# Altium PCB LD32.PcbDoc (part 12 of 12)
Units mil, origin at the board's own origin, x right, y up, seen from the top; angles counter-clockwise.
Board outline 7007.87 x 4368.85 mil, 12 copper layers (Top Layer, Int1 (GND), Int2 (AVDD), Int3 (DVDD), Int4 (GND), Int5 (ST), Int6 (SB), Int8 (AGND), Int7 (AVCC), Int9 (VCCA), Int10 (GND), Bottom Layer), stack 60.136 mil thick; 1165 components, 667 nets, 3910 pads, 2570 vias.
Unrouted connection lines stored in the file: 14.
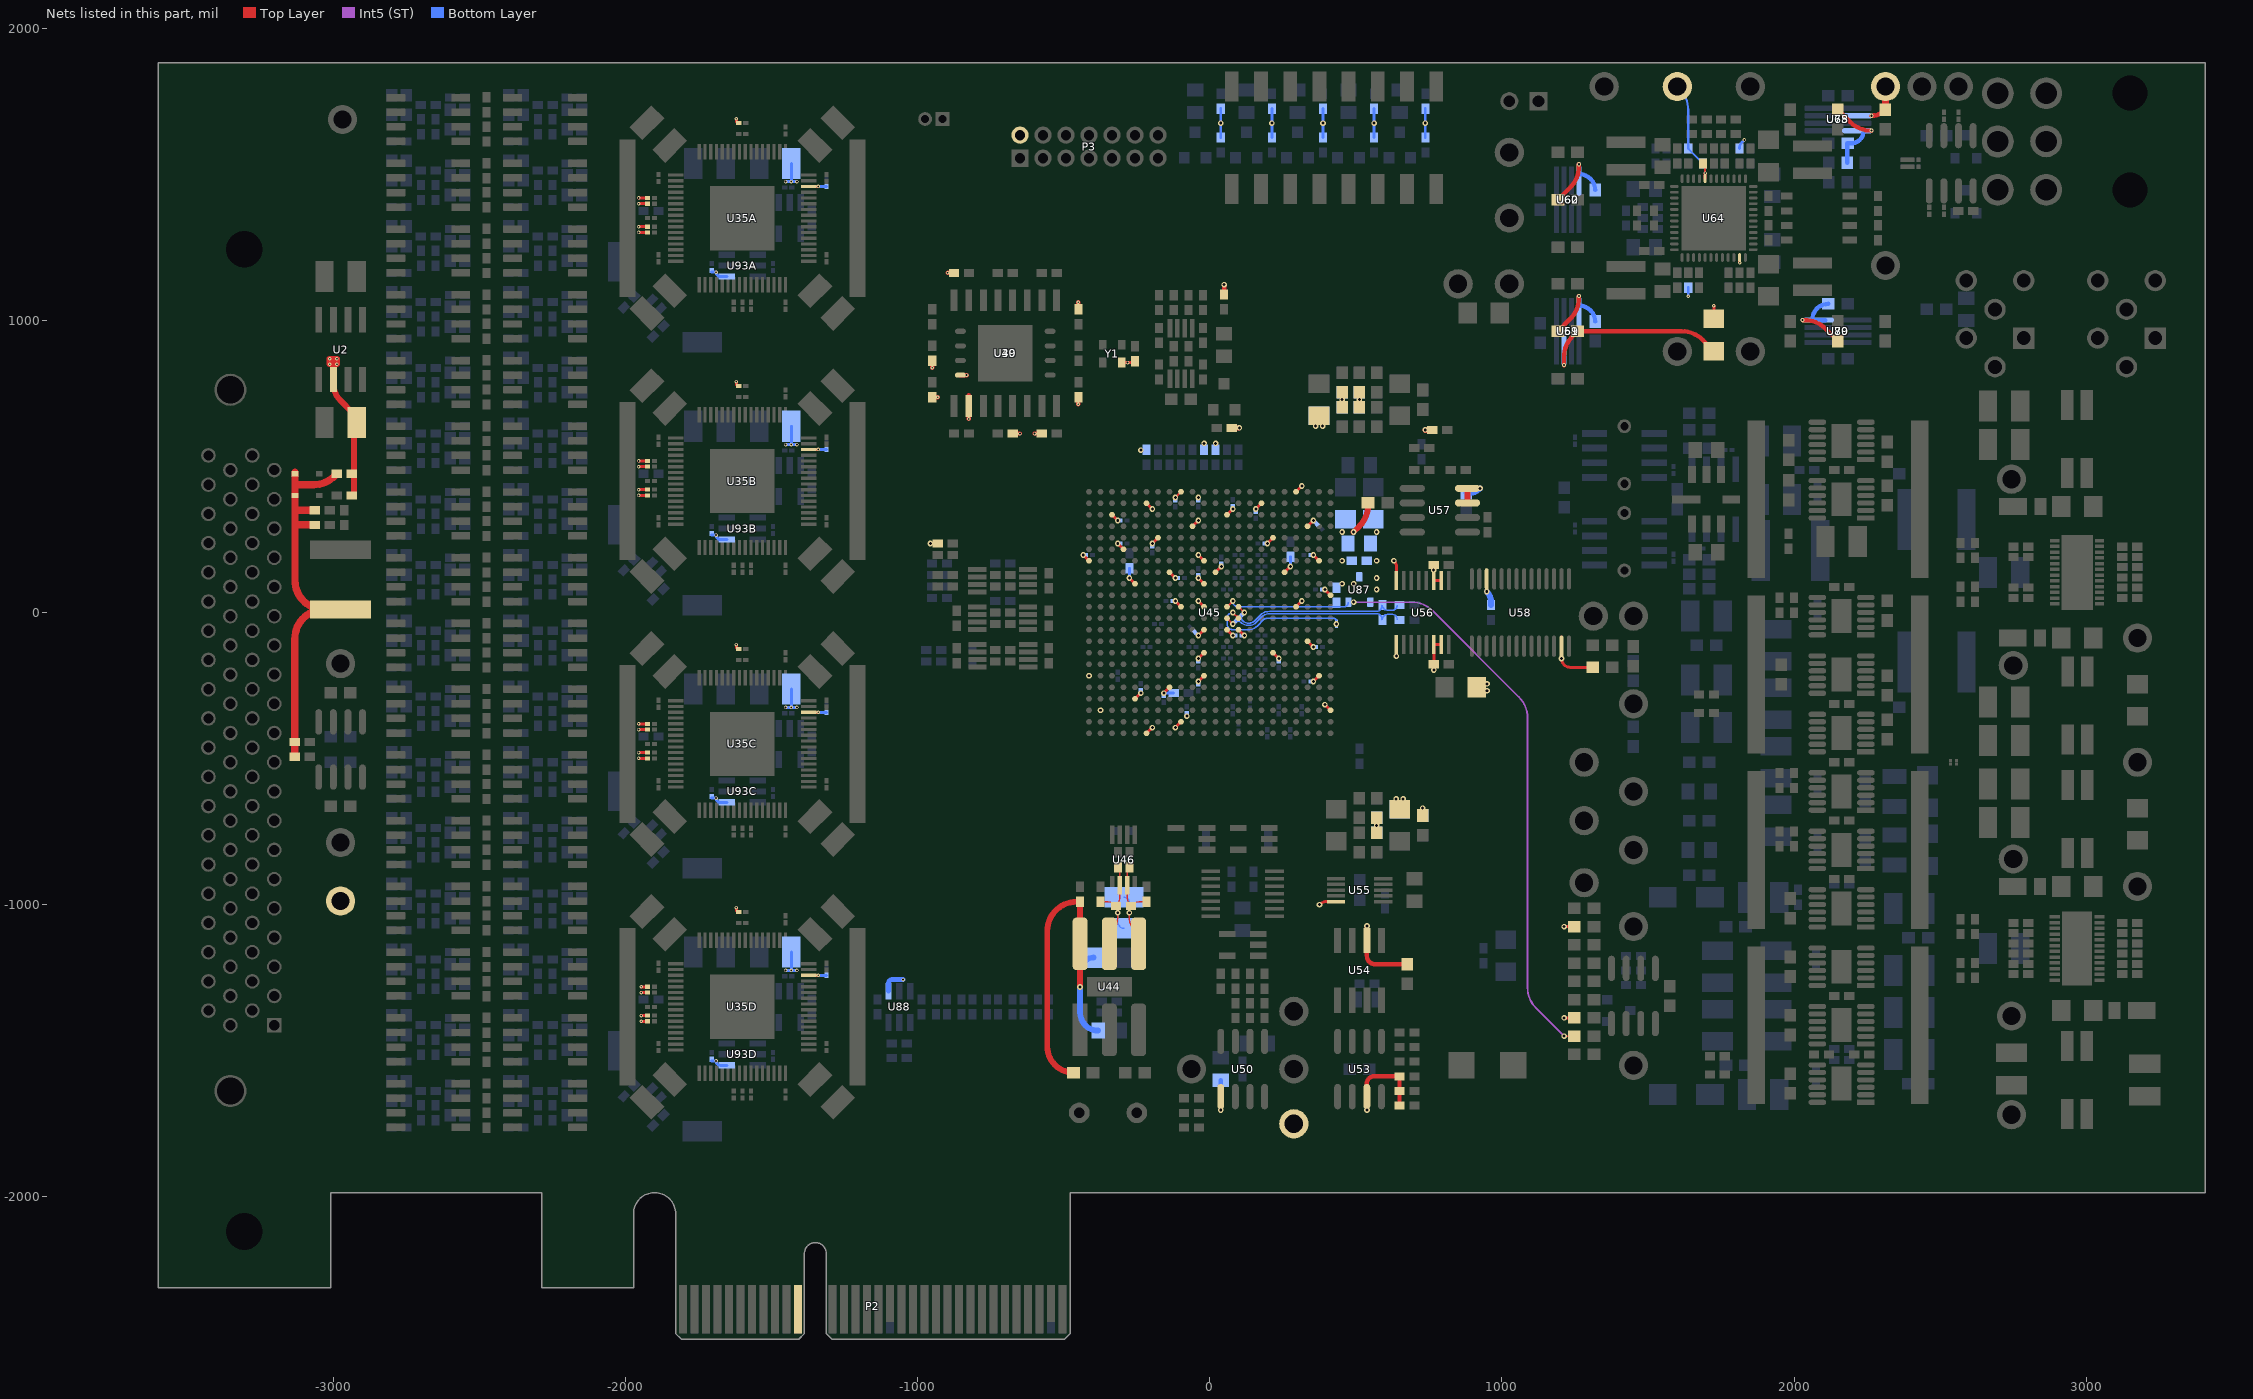
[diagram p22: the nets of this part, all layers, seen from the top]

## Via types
v1: diameter 12, hole 6, Top Layer to Bottom Layer, tented both sides, 1500 vias
v2: diameter 19, hole 10, Top Layer to Bottom Layer, tented both sides, 404 vias
v3: diameter 20, hole 10, Top Layer to Bottom Layer, tented both sides, 337 vias
v4: diameter 14, hole 7, Top Layer to Bottom Layer, tented both sides, 212 vias
v5: diameter 30, hole 15, Top Layer to Bottom Layer, tented both sides, 37 vias
v6: diameter 19.68, hole 7.87, Top Layer to Bottom Layer, 25 vias
v7: diameter 40, hole 20, Top Layer to Bottom Layer, tented both sides, 16 vias
v8: diameter 19.02, hole 10, Top Layer to Bottom Layer, tented both sides, 10 vias
v9: diameter 40, hole 20, Top Layer to Bottom Layer, 9 vias
v10: diameter 60, hole 40, Top Layer to Bottom Layer, 5 vias
v11: diameter 25, hole 13, Top Layer to Bottom Layer, 4 vias
v12: diameter 50, hole 25, Top Layer to Bottom Layer, tented both sides, 4 vias
v13: diameter 35, hole 20, Top Layer to Bottom Layer, 2 vias
v14: diameter 50, hole 25, Top Layer to Bottom Layer, 2 vias
v15: diameter 63, hole 45, Top Layer to Bottom Layer, 1 vias
v16: diameter 14.02, hole 7.01, Top Layer to Bottom Layer, tented both sides, 1 vias
v17: diameter 60, hole 40, Top Layer to Bottom Layer, tented both sides, 1 vias

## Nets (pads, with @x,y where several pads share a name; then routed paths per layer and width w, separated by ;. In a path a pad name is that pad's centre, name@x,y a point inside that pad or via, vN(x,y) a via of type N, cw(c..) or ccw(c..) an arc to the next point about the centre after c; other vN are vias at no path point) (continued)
VCCAUX: C72.2 C74.2 C75.2 C78.2 C79.2 C80.2 C81.2 C84.2 C91.2 C182.2 C185.2 C189.2 C190.2 C199.2 C200.2 C201.2 C202.2 C204.2 C205.2 C206.2 C207.2 C208.2 C209.2 C212.2 C214.2 C227.2 C228.2 C241.2 C247.2 C250.2 C251.2 C252.2 C253.2 C254.2 C256.2 C257.2 C258.2 C259.2 C260.2 C261.2 C263.2 C265.2 C268.1 C269.2 C270.2 C273.2 C287A.1 C287B.1 C287C.1 C287D.1 C291A.2 C291B.2 C291C.2 C291D.2 C307A.2 C307B.2 C307C.2 C307D.2 FR1.2 P3.2 R39A.2 R39B.2 R39C.2 R39D.2 R40A.2 R40B.2 R40C.2 R40D.2 R41A.2 R41B.2 R41C.2 R41D.2 R42A.2 R42B.2 R42C.2 R42D.2 R56A.2 R56B.2 R56C.2 R56D.2 R67.2 R68.2 R71.2 R73.1 R82.2 R85.1 R88.2 R90.2 R96.1 R107.2 R109.1 R189.1 R263.2 R280.2 R281.1 R285.2 R286.1 R288.2 R289.1 R290.2 R291.1 R295.2 R296.1 R297.2 R298.2 R304.2 TP28.1 U35A.62 U35B.62 U35C.62 U35D.62 U39.2 U40.8 U45.A17 U45.AA7 U45.AA17 U45.AB4 U45.AB14 U45.B14 U45.C1 U45.C21 U45.D18 U45.E15 U45.F2 U45.F12 U45.F22 U45.H6 U45.H12 U45.J3 U45.K12 U45.M4 U45.M12 U45.M14 U45.N1 U45.P12 U45.P18 U45.R5 U45.R11 U45.R15 U45.T2 U45.T12 U45.T22 U45.U19 U45.V6 U45.V16 U45.W3 U45.W13 U45.Y10 U45.Y20 U55.10 U65.2 U78.2 U88.1 U93A.1 U93B.1 U93C.1 U93D.1 Y1.4 | length 3834.6
  Top Layer w7.99: v2(-118.11,393.7) U45.AB14@-98.43,413.39
  Top Layer w10: v1(-1955,-499.21) R39C.2@-1933.17,-499.21 ; v1(-1955,-479.53) R40C.2@-1933.17,-479.53 ; v1(-1955,-400.79) R41C.2@-1933.17,-400.79 ; v1(-1955,-381.1) R42C.2@-1933.17,-381.1 ; v1(-1955,400.79) R39B.2@-1933.17,400.79 ; v1(-1955,420.47) R40B.2@-1933.17,420.47 ; v1(-1955,499.21) R41B.2@-1933.17,499.21 ; v1(-1955,518.9) R42B.2@-1933.17,518.9 ; v1(-1955,1300.79) R39A.2@-1933.17,1300.79 ; v1(-1955,1320.47) R40A.2@-1933.17,1320.47 ; v1(-1955,1399.21) R41A.2@-1933.17,1399.21 ; v1(-1955,1418.9) R42A.2@-1933.17,1418.9 ; v1(-1946.08,-1399.21) R39D.2@-1933.17,-1399.21 ; v1(-1946.08,-1379.53) R40D.2@-1933.17,-1379.53 ; v1(-1946.08,-1300.79) R41D.2@-1933.17,-1300.79 ; v1(-1946.08,-1281.1) R42D.2@-1933.17,-1281.1 ; v1(-1620.67,-1009.75) -1620.67,-1016.27 ccw(c-1611.94,-1016.27) R56D.2@-1611.94,-1025 ; v1(-1620.67,-109.75) -1620.67,-116.27 ccw(c-1611.94,-116.27) R56C.2@-1611.94,-125 ; v1(-1620.67,790.25) -1620.67,783.73 ccw(c-1611.94,783.73) R56B.2@-1611.94,775 ; v1(-1620.67,1690.25) -1620.67,1683.73 ccw(c-1611.94,1683.73) R56A.2@-1611.94,1675 ; U35D.62@-1372.5,-1241.73 v1(-1340,-1241.73) ; U35C.62@-1372.5,-341.73 v1(-1340,-341.73) ; U35B.62@-1372.5,558.27 v1(-1340,558.27) ; U35A.62@-1372.5,1458.27 v1(-1340,1458.27) ; v2(-956.69,236.22) R71.2@-931.1,236.22 ; v2(-433.07,196.85) U45.T22@-413.39,177.17 ; U45.Y20@-334.65,334.65 v2(-314.96,314.96) ; v2(-314.96,236.22) U45.U19@-295.28,216.54 ; Y1.4@-302.17,855.32 v1(-281.48,855.32) -267.79,855.32 ccw(c-267.79,872.12) R96.1@-255.91,860.24 ; v2(-275.59,118.11) U45.P18@-255.91,98.43 ; U45.D18@-255.91,-295.28 v2(-236.22,-275.59) ; U45.A17@-216.54,-413.39 v2(-196.85,-393.7) ; U45.AA17@-216.54,374.02 v2(-196.85,354.33) ; v2(-196.85,236.22) U45.V16@-177.17,255.91 ; v2(-157.48,-275.59) U45.E15@-137.8,-255.91 ; U45.R15@-137.8,137.8 v2(-118.11,118.11) ; v2(-118.11,-393.7) U45.B14@-98.43,-374.02 ; v2(-118.11,39.37) U45.M14@-98.43,19.69 ; U45.W13@-59.05,295.28 v2(-39.37,314.96) ; v2(-39.37,-236.22) U45.F12@-19.68,-216.54 ; v2(-39.37,-157.48) U45.H12@-19.68,-137.8 ; v2(-39.37,-78.74) U45.K12@-19.68,-59.06 ; v2(-39.37,39.37) U45.M12@-19.68,19.69 ; v2(-39.37,118.11) U45.P12@-19.68,98.43 ; v2(-39.37,196.85) U45.T12@-19.68,177.17 ; U45.R11@19.69,137.8 v2(39.37,157.48) ; U45.Y10@59.06,334.65 v2(78.74,354.33) ; v2(157.48,354.33) U45.AA7@177.17,374.02 ; v2(196.85,236.22) U45.V6@216.54,255.91 ; U45.H6@216.54,-137.8 v2(236.22,-157.48) ; U45.R5@255.91,137.8 v2(275.59,157.48) ; U45.M4@295.28,19.69 v2(314.96,39.37) ; U45.AB4@295.28,413.39 v2(314.96,433.07) ; U45.J3@334.65,-98.43 v2(354.33,-118.11) ; U45.W3@334.65,295.28 v2(354.33,314.96) ; v2(354.33,-236.22) U45.F2@374.02,-216.54 ; v2(354.33,196.85) U45.T2@374.02,177.17 ; v3(375,-1000) cw(c400.66,-1025.66) 400.66,-989.37 U55.10@431.79,-989.37 ; v2(393.7,-314.96) U45.C1@413.39,-334.65 ; v2(393.7,78.74) U45.N1@413.39,59.06 ; C74.2@452.76,702.76 v2(452.76,728.35) C75.2@452.76,753.94 ; C78.2@511.81,702.76 C79.2@511.81,753.94 ; C80.2@570.87,-753.94 C81.2@570.87,-702.76
  Top Layer w15: R67.2@-950,736.91 v1(-931.1,736.91) ; v1(-950,837.5) R68.2@-950,861.91 ; v1(-897.46,1162.5) R73.1@-875.59,1162.5 ; U40.8@-853.54,812.5 v1(-832.4,812.5) ; v1(-825,662.5) U39.2@-825,706.4 U39.2@-825,743.59 ; R82.2@-674.41,612.5 v1(-650,612.5) ; v1(-600,612.5) R85.1@-575.59,612.5 ; v1(-450,713.09) R88.2@-450,736.91 ; R90.2@-450,1038.09 v1(-450,1061.91)
  Top Layer w15.98: R109.1@49.21,1088.58 v2(49.21,1122.05) ; R107.2@74.8,631.76 v2(100.93,631.76) ; v4(2264.86,1700.3) ccw(c2264.86,1765.4) 2310.9,1719.36 R189.1@2312.5,1720.96
  Top Layer w25: R189.1@2312.5,1720.96 TP28.1@2312.5,1800
  Bottom Layer w10: C307D.2@-1705,-1535 v1(-1690,-1535) ccw(c-1675.1,-1535) -1675.1,-1549.9 U93D.1@-1653.15,-1549.9 ; C307C.2@-1705,-635 v1(-1690,-635) ccw(c-1675.1,-635) -1675.1,-649.9 U93C.1@-1653.15,-649.9 ; C307B.2@-1705,265 v1(-1690,265) ccw(c-1675.1,265) -1675.1,250.1 U93B.1@-1653.15,250.1 ; C307A.2@-1705,1165 v1(-1690,1165) ccw(c-1675.1,1165) -1675.1,1150.1 U93A.1@-1653.15,1150.1 ; v1(-1452.21,-1225) v1(-1432.38,-1225) ; v1(-1452.21,-325) v1(-1432.38,-325) ; v1(-1452.21,575) v1(-1432.38,575) ; v1(-1452.21,1475) v1(-1432.38,1475) ; C291D.2@-1432.38,-1162.5 v1(-1432.38,-1225) ; C291C.2@-1432.38,-262.5 v1(-1432.38,-325) ; C291B.2@-1432.38,637.5 v1(-1432.38,575) ; C291A.2@-1432.38,1537.5 v1(-1432.38,1475) ; v1(-1413.13,-1225) v1(-1432.38,-1225) ; v1(-1413.13,-325) v1(-1432.38,-325) ; v1(-1413.13,575) v1(-1432.38,575) ; v1(-1413.13,1475) v1(-1432.38,1475) ; v1(-1340,-1241.73) -1326.42,-1241.73 -1312.5,-1241.73 C287D.1@-1312.5,-1241.94 ; v1(-1340,-341.73) -1326.42,-341.73 -1312.5,-341.73 C287C.1@-1312.5,-341.94 ; v1(-1340,558.27) -1326.42,558.27 -1312.5,558.27 C287B.1@-1312.5,558.06 ; v1(-1340,1458.27) -1326.42,1458.27 -1312.5,1458.27 C287A.1@-1312.5,1458.06 ; v2(-275.59,118.11) C268.1@-275.59,151.57 ; v2(-157.48,-275.59) -157.48,-275.72 C257.2@-124.02,-275.72 ; R295.2@37.5,1625.59 v2(37.5,1675) R296.1@37.5,1724.41 ; R290.2@212.5,1625.59 v2(212.5,1675) R291.1@212.5,1724.41 ; v2(275.59,157.48) C212.2@275.59,190.94 ; R288.2@387.5,1625.59 v2(387.5,1675) R289.1@387.5,1724.41 ; C201.2@452.76,702.76 v2(452.76,728.35) C202.2@452.76,753.94 ; C199.2@511.81,702.76 v2(511.81,728.35) C200.2@511.81,753.94 ; R285.2@562.5,1625.59 v2(562.5,1675) R286.1@562.5,1724.41 ; C189.2@570.87,-753.94 v2(570.87,-728.35) C190.2@570.87,-702.76 ; R280.2@737.5,1625.59 v2(737.5,1675) R281.1@737.5,1724.41 ; v1(1637.5,1082.5) R263.2@1637.5,1111.91
  Bottom Layer w15.98: U88.1@-1099.9,-1296.85 -1099.9,-1268.65 cw(c-1087.5,-1268.65) -1087.5,-1256.25 v1(-1050,-1256.25)
  other v2: 728.35,-669.29 637.8,-637.8 661.42,-637.8 -78.74,-354.33 -374.02,-334.65 -413.39,-216.54 -39.37,393.7 -236.22,555.9 -19.68,578.74 19.69,578.74 362.2,637.8 385.83,637.8
  other v3: 948.82,-267.72 948.82,-244.09
VCOCLK_N: R92.2 R95.1 R97.1 TP40.1 U44.4 U46.3 | length 372.6
  Top Layer w5: R95.1@-275.59,-872.05 ccw(c-258.96,-888.68) -282.48,-888.68 U46.3@-282.48,-933.27 -282.48,-973.05 ccw(c-238.79,-973.05) R92.2@-269.68,-1003.94 ; U44.4@-246.46,-1110.24 cw(c-176.12,-1039.9) -275.59,-1039.9 v3(-275.59,-1027.56) -275.59,-1018.19 cw(c-255.43,-1018.19) R92.2@-269.68,-1003.94 ; R97.1@-216.54,-990.16 -236.42,-990.16 ccw(c-236.42,-1037.2) R92.2@-269.68,-1003.94
  Bottom Layer w5: TP40.1@-293.75,-975 cw(c-293.75,-993.16) -275.59,-993.16 v3(-275.59,-1027.56)
VCOCLK_P: R91.2 R92.1 R93.2 TP39.1 U44.5 U46.2 | length 377.1
  Top Layer w5: R91.2@-374.02,-990.16 -354.13,-990.16 cw(c-354.13,-1037.2) R92.1@-320.87,-1003.94 ; U44.5@-346.46,-1110.24 -344.25,-1108.03 ccw(c-414.96,-1037.32) -314.96,-1037.32 v3(-314.96,-1027.56) -314.96,-1018.19 ccw(c-335.12,-1018.19) R92.1@-320.87,-1003.94 ; R93.2@-314.96,-872.05 cw(c-331.59,-888.68) -308.07,-888.68 U46.2@-308.07,-933.27 -308.07,-973.05 cw(c-351.76,-973.05) R92.1@-320.87,-1003.94
  Bottom Layer w5: v3(-314.96,-1027.56) -314.96,-1058.79 ccw(c-292.5,-1058.79) TP39.1@-292.5,-1081.25
VREF1.28: C1.2 C2.1 D1.1 D2.2 R1.2 R2.2 R3.2 R5.2 | length 1436.7
  Top Layer w25: R1.2@-3131.84,-493.75 R2.2@-3131.84,-443.75 -3131.84,-89.86 cw(c-3031.84,-89.86) C1.2@-3031.84,10.14 ; D2.2@-3131.25,481.25 -3131.25,437.5 ; R3.2@-3063.09,300 -3131.25,300 ; C2.1@-3063.09,350 -3131.25,350 ; R5.2@-2988.09,475 -2996.3,466.79 cw(c-3067.01,537.5) -3067.01,437.5 -3131.25,437.5 ; C1.2@-2975,10.14 C1.2@-3031.25,10.14 ; -3131.25,300 -3131.25,350 ; -3131.25,300 -3131.25,110.14 ccw(c-3031.25,110.14) C1.2@-3031.84,10.14 ; -3131.25,350 -3131.25,437.5 ; C1.2@-3031.84,10.14 ccw(c-3031.25,110.14) C1.2@-3031.25,10.14 ; C1.2@-3031.84,10.14 C1.2@-3031.25,10.14
VREF-COM: C5.2 R4.1 R5.1 TP1.1 U2.6 | length 541
  Top Layer w20: R4.1@-2929.04,400 C5.2@-2929.04,626.07 ; C5.2@-2919.88,650 ccw(c-2967.88,650) -2933.94,683.94 -2975,725 cw(c-2914.64,785.36) -3000,785.36 U2.6@-3000,797.64 -3000,850 ; -3000,850 v1(-2987.5,850) v1(-2987.5,868.75) v1(-3012.5,868.75) v1(-3012.5,850) -3000,850
VREF-PH: C86.2 C87.2 C89.2 C248.1 R115.2 TP5.1 U50.5 U53.3 U54.6 | length 674.4
  Top Layer w15: v3(37.5,-1702.5) U50.5@37.5,-1656.99 ; U53.3@537.5,-1656.99 537.5,-1612.5 cw(c562.5,-1612.5) 562.5,-1587.5 C87.2@649.41,-1587.5 C86.2@649.41,-1637.5 R115.2@649.41,-1687.5 ; v3(537.5,-1072.5) U54.6@537.5,-1122.64 537.5,-1175 ccw(c566.54,-1175) 566.54,-1204.04 C89.2@675,-1204.04
  Bottom Layer w15: v3(37.5,-1702.5) C248.1@37.5,-1600.89
  other v3: 537.5,-1702.5
VREG: C108.1 FR3.1 R250.2 R260.2 R264.2 TP24.1 U64.23 U64.44 | length 489.9
  Top Layer w7: C108.1@1687.5,1536.91 cw(c1668.25,1517.66) 1695.47,1517.66 v1(1695.47,1504.04)
  Top Layer w10: U64.44@1695.47,1484.84 v1(1695.47,1504.04) ; FR3.1@1725,1005.12 v1(1725,1050.1) ; v1(1813.58,1197.36) U64.23@1813.58,1215.16
  Bottom Layer w7: TP24.1@1600,1800 1608.21,1791.79 cw(c1537.5,1721.08) 1637.5,1721.08 R264.2@1637.5,1590 ; R264.2@1637.5,1588.09 R264.2@1637.5,1590 ; v1(1695.47,1504.04) 1695.47,1536.91 R260.2@1687.5,1536.91 ccw(c1686.07,1536.91) 1687.08,1537.92 1639.27,1585.73 cw(c1643.54,1590) R264.2@1637.5,1590
  Bottom Layer w10: R250.2@1812.5,1588.09 cw(c1841.25,1588.09) 1820.92,1608.42 v1(1830,1617.5)
VREG2: C178.1 FR3.2 U59.7 U61.7 | length 620.8
  Top Layer w15: v4(1212.2,846.76) 1212.2,874.82 cw(c1312.2,874.82) 1241.49,945.53 C178.1@1258.46,962.5 1615.96,962.5 cw(c1615.96,862.5) 1686.67,933.21 FR3.2@1725,894.88
VVCO: C64.2 C267.2 FR9.1 R87.2 U44.6 | length 1308.5
  Top Layer w20: R87.2@-466.54,-1574.8 cw(c-466.54,-1485.09) -556.25,-1485.09 -556.25,-1090.16 cw(c-456.25,-1090.16) -456.25,-990.16 C64.2@-444.88,-990.16 -444.32,-990.72 U44.6@-444.32,-1138.94 ; v3(-443.75,-1281.25) -444.32,-1281.25 U44.6@-444.32,-1138.94 ; U44.6@-443.75,-1139.51 U44.6@-444.32,-1138.94
  Bottom Layer w20: FR9.1@-397.62,-1181.25 ccw(c-397.62,-1227.38) -443.75,-1227.38 v3(-443.75,-1281.25) -443.75,-1369.64 ccw(c-382.14,-1369.64) C267.2@-382.14,-1431.25
WAKE#: P2.B11
XADC_N: C187.2 C233.1 R283.2 U45.M9 | length 625.1
  Top Layer w5: U45.M9@98.43,19.69 v2(118.11,0)
  Bottom Layer w5: C233.1@107.61,-10.5 107.61,-14.03 ccw(c129.78,-14.03) 114.1,-29.71 114.69,-30.29 ccw(c128.35,-16.63) 128.35,-35.95 137.8,-35.95 ccw(c137.8,-16.47) 151.57,-30.24 172.5,-9.31 cw(c204.64,-41.45) 204.64,4 572.5,4 ccw(c572.5,19.56) 588.05,19.56 cw(c596.59,19.56) C187.2@590.55,25.59 ccw(c608.64,25.59) 608.64,7.5 624.04,7.5 ccw(c624.04,25) R283.2@641.54,25
XADC_P: C187.1 C233.2 R282.2 U45.L10 | length 633.4
  Top Layer w5: U45.L10@59.06,-19.68 v2(78.74,-39.37)
  Bottom Layer w5: C233.2@89.24,-28.87 92.77,-28.87 cw(c92.77,-51.04) 108.45,-35.36 109.03,-35.95 ccw(c128.35,-16.63) 128.35,-43.95 137.8,-43.95 ccw(c137.8,-16.47) 157.23,-35.9 178.16,-14.97 cw(c204.64,-41.45) 204.64,-4 572.5,-4 cw(c572.5,-19.55) 588.05,-19.55 ccw(c596.59,-19.55) C187.1@590.55,-25.59 cw(c609.9,-25.59) 609.9,-6.24 624.04,-6.24 cw(c624.04,-23.74) 641.54,-23.74 R282.2@641.54,-25
XADC_REF_N: U45.L9 W3.2 | length 482.4
  Top Layer w5: v2(78.74,0) U45.L9@98.43,-19.68
  Bottom Layer w5: v2(78.74,0) ccw(c78.74,-19.68) 59.06,-19.68 59.06,-39.37 ccw(c78.74,-39.37) 78.74,-59.06 129.64,-59.06 ccw(c129.88,-11.44) 163.55,-45.11 183.41,-25.25 cw(c196.85,-38.69) 196.85,-19.68 423.88,-19.68 cw(c423.88,-28.87) W3.2@433.07,-28.87
XADC_REF_P: C203.1 R136.1 U45.M10 U87.2 | length 2391.2
  Top Layer w5: U45.M10@59.06,19.69 v2(78.74,39.37) ; v8(1212.5,-1450) R136.1@1247.79,-1450
  Int5 (ST) w6: v2(492.13,35.43) 691.9,35.43 cw(c691.9,-64.57) 762.61,6.14 1058.21,-289.46 cw(c987.5,-360.17) 1087.5,-360.17 1087.5,-1283.58 ccw(c1187.5,-1283.58) 1116.79,-1354.29 v8(1212.5,-1450)
  Bottom Layer w5: v2(78.74,39.37) ccw(c98.43,39.37) 98.43,19.69 458.66,19.69 ccw(c458.66,35.43) U87.2@474.41,35.43
XADCGND: C93.2 C94.1 C95.1 C152.2 C155.2 C178.2 C179.2 C180.2 C193.2 C197.2 C203.2 C234.1 FR8.2 R114.1 R124.2 R125.2 R130.2 R135.2 R137.2 R176.2 R185.2 R230.2 R279.1 U45.K9 U56.2 U56.3 U56.8 U56.9 U56.14 U56.15 U57.3 U57.4 U58.12 U58.27 U59.4 U60.4 U61.4 U62.4 U65.4 U78.4 U79.4 U80.4 U87.3 W3.1 | length 1950.6
  Top Layer w10: U45.K9@98.43,-59.06 v2(118.11,-78.74) ; v2(629.92,177.17) cw(c608.54,155.78) 638.78,155.78 U56.8@638.78,109.25 ; C94.1@766.73,-177.17 U56.14@766.73,-109.25 U56.15@792.32,-109.25 ; U56.3@766.73,109.25 U56.2@792.32,109.25 ; v3(947.83,71.77) U58.12@947.83,115.16 ; U58.27@1203.74,-83.76 U58.27@1203.74,-115.16 v3(1203.74,-157.48) ccw(c1233.76,-157.48) 1233.76,-187.5 R137.2@1310.29,-187.5 ; v8(1212.5,-1387.5) R130.2@1247.79,-1387.5 ; v8(1212.5,-1075) R135.2@1247.79,-1075
  Top Layer w15: C178.2@1191.54,962.5 1234.1,1005.06 ccw(c1163.39,1075.77) 1263.39,1075.77 v4(1263.39,1083.03) ; C179.2@1191.54,1412.5 1234.1,1455.06 ccw(c1163.39,1525.77) 1263.39,1525.77 v4(1263.39,1534.3) ; v4(2029.27,1000.89) 2036.73,1000.89 cw(c2036.73,900.89) 2107.44,971.6 C152.2@2150,929.04 ; C155.2@2150,1720.96 2192.56,1678.4 ccw(c2263.27,1749.11) 2263.27,1649.11 v4(2264.86,1649.11)
  Top Layer w20: v2(492.13,275.59) 512.25,295.71 ccw(c441.54,366.42) 541.54,366.42 R114.1@541.54,375 ; v2(737.5,625) C93.2@761.91,625 ; U57.3@881.99,375 U57.4@881.99,425
  Bottom Layer w15: v4(1263.39,1083.03) U59.4@1263.39,1050.1 1264.62,1050.1 cw(c1264.62,995.96) R124.2@1318.75,995.96 ; v4(1263.39,1534.3) U60.4@1263.39,1500.1 1264.62,1500.1 cw(c1264.62,1445.96) R125.2@1318.75,1445.96 ; v4(2029.27,1000.89) U79.4@2062.4,1000.89 ; U80.4@2106.67,1000.89 U79.4@2062.4,1000.89 ; R185.2@2116.54,1056.25 ccw(c2116.54,1002.12) 2062.4,1002.12 U79.4@2062.4,1000.89 ; R230.2@2181.25,1539.71 2181.25,1604.04 cw(c2183.46,1604.04) R176.2@2183.46,1606.25 2195.96,1606.25 ccw(c2195.96,1647.88) 2237.6,1647.88 U65.4@2237.6,1649.11
  Bottom Layer w20: R279.1@877.5,408.46 885.08,408.46 ccw(c885.08,464.92) v2(925,425) ; v3(947.83,71.77) cw(c912.43,36.37) 962.5,36.37 C180.2@962.5,25.59
  other v2: 766.73,-196.85 638.78,-149.12 433.07,-39.37 452.76,98.43 492.13,98.43 766.26,145 452.76,177.17 452.76,275.59
XADCVCC: C193.1 C197.1 C234.2 FR7.2 U45.K10 U87.1 | length 27.8
  Top Layer w10: U45.K10@59.06,-59.06 v2(78.74,-78.74)
  other v2: 570.87,78.74 570.87,118.11 570.87,177.17 570.87,275.59
pads on no net: J2.MH1 J2.MH2 P2.A19 P2.A32 P2.B12 P2.B17 P2.B30 P3.12 P3.14 U2.1 U2.3 U2.5 U2.7 U2.8 U39.4 U39.5 U39.6 U39.11 U39.12 U39.13 U39.14 U41.1 U41.4 U42.1 U43.1 U43.4 U45.A13 U45.A14 U45.A16 U45.A20 U45.AA4 U45.AA9 U45.AA10 U45.AA11 U45.AA13 U45.AA14 U45.AA15 U45.AA16 U45.AB10 U45.AB11 U45.AB12 U45.AB13 U45.AB15 U45.AB16 U45.AB17 U45.AB18 U45.B13 U45.B15 U45.B16 U45.C2 U45.C13 U45.C14 U45.C15 U45.C17 U45.C18 U45.D1 U45.D2 U45.D14 U45.D15 U45.D16 U45.D17 U45.D19 U45.D20 U45.E1 U45.E2 U45.E3 U45.E10 U45.E13 U45.E14 U45.E16 U45.E17 U45.E18 U45.E19 U45.E22 U45.F1 U45.F3 U45.F4 U45.F10 U45.F13 U45.F14 U45.F15 U45.F16 U45.F18 U45.F19 U45.G1 U45.G2 U45.G3 U45.G4 U45.G17 U45.G18 U45.H2 U45.H3 U45.H4 U45.H5 U45.H14 U45.H15 U45.H17 U45.H18 U45.J2 U45.J4 U45.J5 U45.J6 U45.J14 U45.J15 U45.J16 U45.J17 U45.K2 U45.K3 U45.K4 U45.K6 U45.K13 U45.K14 U45.K16 U45.K17 U45.L3 U45.L4 U45.L5 U45.L6 U45.L13 U45.L14 U45.L15 U45.L16 U45.L18 U45.M2 U45.M3 U45.M5 U45.M6 U45.M13 U45.M15 U45.M16 U45.M17 U45.M18 U45.M20 U45.N2 U45.N3 U45.N4 U45.N5 U45.N13 U45.N14 U45.N15 U45.N17 U45.N18 U45.N19 U45.N20 U45.P1 U45.P2 U45.P4 U45.P5 U45.P6 U45.P14 U45.P15 U45.P16 U45.P17 U45.P19 U45.R1 U45.R6 U45.R14 U45.R16 U45.R17 U45.R18 U45.T3 U45.T4 U45.T5 U45.T6 U45.T14 U45.T15 U45.T16 U45.T18 U45.T20 U45.U3 U45.U5 U45.U6 U45.U7 U45.U15 U45.U16 U45.U17 U45.V4 U45.V5 U45.V7 U45.V8 U45.V9 U45.V10 U45.V13 U45.V14 U45.V15 U45.W1 U45.W6 U45.W7 U45.W9 U45.W10 U45.W11 U45.W12 U45.W14 U45.W15 U45.W16 U45.W17 U45.Y1 U45.Y4 U45.Y6 U45.Y7 U45.Y8 U45.Y11 U45.Y12 U45.Y13 U45.Y14 U45.Y16 U45.Y17 U45.Y19 U46.1 U46.4 U47.1 U49.6 U49.8 U54.1 U54.3 U54.5 U54.7 U54.8 U58.2 U58.3 U58.13 U66.4 U66.7 U68.5 U69.3 U70.3 U71.3 U72.3 U73.3 U73.5 U74.3 U75.3 U76.3 U76.5 U82.4 U82.9 U82.14 U83.4 U83.9 U83.14 U84.1 U84.5 U84.8 U85.1 U85.5 U85.8 U86.1 U86.5 U86.8

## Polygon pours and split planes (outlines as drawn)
AGND on Bottom Layer "AGND_L12_P413" (solid, pour order 413): 1377.95,-1800 1377.95,775 2418.75,775 2418.75,-1800
GND on Bottom Layer "GND_L12_P377" (solid, remove dead copper, pour order 377): 1348.43,1868.75 -1150,1868.75 -1150,-1850.01 -1237.49,-1937.5 -787.5,-1937.5 -650,-1800 1348.43,-1800
GND on Bottom Layer "GND_L12_P414" (solid, pour order 414): 2457.85,-1800 3276.6,-1800 3276.6,775 2457.85,775
AGND on Bottom Layer "AGND_L12_P323" (solid, remove dead copper, pour order 323): -3587.5,1867.5 -1175,1867.5 -1175,-1937.5 -3587.5,-1937.5
EXT12V on Bottom Layer "EXT12V_L12_P417" (solid, pour order 417): 2362.5,1475.23 2412.5,1475.23 2412.5,1533.75 2362.5,1533.75 2362.5,1515.23
12V on Bottom Layer "12V_L12_P416" (solid, pour order 416): 2362.5,1541.25 2412.5,1541.25 2412.5,1600 2362.5,1600 2362.5,1581.25
XADCGND on Bottom Layer "XADCGND_L12_P300" (solid, pour order 300): 413.39,66.93 523.62,66.93 523.62,145.67 503.94,165.35 503.94,354.33 413.39,354.33
XADCVCC on Bottom Layer "XADCVCC_L12_P321" (solid, pour order 321): 519.69,354.33 519.69,157.48 531.5,145.67 531.5,19.69 570.87,19.69 570.87,59.06 594.49,82.68 594.49,354.33
GND on Bottom Layer "GND_L12_P375" (solid, pour order 375): 1897.5,1522.5 1897.5,1467.5 1952.5,1467.5 1952.5,1522.5
VCC on Bottom Layer "VCC_L12_P376" (solid, pour order 376): -50,-1050 -50,-920 275,-920 275,-1050
GND on Bottom Layer "GND_L12_P374" (solid, pour order 374): 1952.5,1177.5 1952.5,1232.5 1897.5,1232.5 1897.5,1177.5
AGND on Top Layer "NONET_L-01_P-001" (solid, pour order 412): 2531.25,-1781.25 1631.25,-1781.25 1631.25,775 2531.25,775
AGND on Top Layer "AGND_L01_P301" (solid, remove dead copper, pour order 301): -3556.25,1867.5 -1086.25,1867.5 -1086.25,-1929 -2016.82,-1929 -3556.25,-1929
NetD3_2 on Top Layer "NETD3_2_L01_P419" (solid, pour order 419): 2412.5,1533.75 2362.5,1533.75 2362.5,1475 2412.5,1475 2412.5,1493.75
12V on Top Layer "12V_L01_P418" (solid, pour order 418): 2362.5,1541.25 2412.5,1541.25 2412.5,1600 2362.5,1600 2362.5,1581.25
GND on Top Layer "GND_L01_P409" (solid, pour order 409): 2706.25,-500 2706.25,-243.75 2556.25,-243.75 2556.25,-500
GND on Top Layer "GND_L01_P408" (solid, pour order 408): 3131.25,651.25 2977.5,651.25 2977.5,775 3131.25,775
GND on Top Layer "GND_L01_P410" (solid, pour order 410): 2706.27,518.75 2706.27,775 2556.27,775 2556.27,518.75
NetC123_1 on Top Layer "NETC123_1_L01_P405" (solid, pour order 405): 2725,-525 2960,-525 2960,-650 2725,-650
NetC124_1 on Top Layer "NETC124_1_L01_P393" (solid, pour order 393): 2960,-500 2725,-500 2725,-375 2960,-375
GND on Top Layer "GND_L01_P404" (solid, pour order 404): 3075,-500 2977.5,-500 2977.5,-375 3075,-375
GND on Top Layer "GND_L01_P402" (solid, pour order 402): 2556.25,-781.42 2706.25,-781.42 2706.25,-525 2556.25,-525
GND on Top Layer "GND_L01_P406" (solid, pour order 406): 2977.5,-525 3075,-525 3075,-650 2977.5,-650
GND on Top Layer "GND_L01_P403" (solid, pour order 403): 2687.5,-1550 2800,-1550 2800,-1325 2687.5,-1325
GND on Top Layer "GND_L01_P394" (solid, pour order 394): 3141.25,-1587.5 3141.25,-1325 3256.25,-1325 3256.25,-1587.5
NetC123_1 on Top Layer "NETC123_1_L01_P392" (solid, pour order 392): 2978.75,-1662.5 3141.25,-1662.5 3141.25,-1612.5 3256.25,-1612.5 3256.25,-1781.25 2978.75,-1781.25
NetC124_1 on Top Layer "NETC124_1_L01_P407" (solid, pour order 407): 2960,651.25 2718.75,651.25 2718.75,775 2960,775
SW-10V on Top Layer "SW-10V_L01_P401" (solid, pour order 401): 2556.25,-1781.25 2556.25,-1243.75 2581.25,-1243.75 2581.25,-1325 2668.75,-1325 2668.75,-1781.25
NetC136_1 on Top Layer "NETC136_1_L01_P400" (solid, pour order 400): 2818.75,312.5 2818.75,531.25 2960,531.25 2960,312.5
NetC134_1 on Top Layer "NETC134_1_L01_P399" (solid, pour order 399): 2818.75,-975 2818.75,-768.75 2960,-768.75 2960,-975
NetC136_2 on Top Layer "NETC136_2_L01_P398" (solid, pour order 398): 2881.25,243.75 2903.75,243.75 2903.75,275 3033.75,275 3033.75,243.75 3056.25,243.75 3056.25,531.25 2977.5,531.25 2977.5,293.75 2881.25,293.75
NetC134_2 on Top Layer "NETC134_2_L01_P397" (solid, pour order 397): 2881.25,-1043.75 2903.75,-1043.75 2903.75,-1012.5 3033.75,-1012.5 3033.75,-1043.75 3056.25,-1043.75 3056.25,-768.75 2977.5,-768.75 2977.5,-993.75 2881.25,-993.75
NetC126_1 on Top Layer "NETC126_1_L01_P396" (solid, pour order 396): 2556.25,500 2718.75,500 2718.75,630 2806.25,630 2806.25,312.5 2581.25,312.5 2581.25,237.5 2556.25,237.5
SW+10V on Top Layer "SW+10V_L01_P395" (solid, pour order 395): 2806.25,-665 2806.25,-975 2581.25,-975 2581.25,-1050.1 2556.25,-1049.92 2556.25,-800 2725,-800 2725,-665
NetC125_2 on Top Layer "NETC125_2_L01_P391" (solid, pour order 391): 2556.25,-226.25 2725,-226.25 2725,-359.89 2806.25,-359.89 2806.25,-37.5 2581.25,-37.5 2581.25,37.5 2556.25,37.5 2556.25,-37.5
SW-10V on Top Layer "SW-10V_L01_P390" (solid, pour order 390): 2556.25,-1781.25 2958.75,-1781.25 2958.75,-1662.5 2800,-1662.5 2800,-1575 2556.25,-1575
NetC135_1 on Top Layer "NETC135_1_L01_P389" (solid, pour order 389): 2818.75,-256.25 2818.75,-37.5 2960,-37.5 2960,-256.25
NetC133_1 on Top Layer "NETC133_1_L01_P388" (solid, pour order 388): 2978.75,-1537.5 2978.75,-1325 3118.75,-1325 3118.75,-1537.5
NetC135_2 on Top Layer "NETC135_2_L01_P387" (solid, pour order 387): 2881.25,31.25 2881.25,-18.75 2977.5,-18.75 2977.5,-256.25 3056.25,-256.25 3056.25,31.25 3033.75,31.25 3033.75,0 2903.75,0 2903.75,31.25
NetC133_2 on Top Layer "NETC133_2_L01_P386" (solid, pour order 386): 2881.25,-1256.25 2881.25,-1325 2881.25,-1537.5 2958.75,-1537.5 2958.75,-1306.25 3056.25,-1306.25 3056.25,-1256.25 3033.75,-1256.25 3033.75,-1287.5 2903.75,-1287.5 2903.75,-1256.25
NetC115_2 on Top Layer "NETC115_2_L01_P366" (solid, pour order 366): 2137.23,1535.47 2137.23,1362.97 1987.23,1362.97 1987.23,1535.47
NetC114_2 on Top Layer "NETC114_2_L01_P365" (solid, pour order 365): 1987.5,1165 1987.5,1337.5 2137.5,1337.5 2137.5,1165
AVCC3.3V on Top Layer "AVCC3.3V_L01_P249" (solid, pour order 249): -1833.77,-1533.73 -1783.75,-1583.75 -1815,-1615 -1865.02,-1564.98
DVDD1.2V on Top Layer "DVDD1.2V_L01_P257" (solid, pour order 257): -1416.2,-1583.7 -1366.36,-1533.86 -1335.11,-1565.11 -1384.95,-1614.95
DVDD1.2V on Top Layer "DVDD1.2V_L01_P253" (solid, pour order 253): -1878.75,-1146.25 -1803.75,-1071.25 -1772.5,-1102.5 -1847.5,-1177.5
AVCC3.3V on Top Layer "AVCC3.3V_L01_P261" (solid, pour order 261): -1352.5,-1177.5 -1427.5,-1102.5 -1396.25,-1071.25 -1321.25,-1146.25
AVCC3.3V on Top Layer "AVCC3.3V_L01_P248" (solid, pour order 248): -1846.25,-621.25 -1771.25,-696.25 -1802.5,-727.5 -1877.5,-652.5
DVDD1.2V on Top Layer "DVDD1.2V_L01_P256" (solid, pour order 256): -1428.75,-696.25 -1353.75,-621.25 -1322.5,-652.5 -1397.5,-727.5
DVDD1.2V on Top Layer "DVDD1.2V_L01_P252" (solid, pour order 252): -1878.75,-246.25 -1803.75,-171.25 -1772.5,-202.5 -1847.5,-277.5
AVCC3.3V on Top Layer "AVCC3.3V_L01_P260" (solid, pour order 260): -1352.5,-277.5 -1427.5,-202.5 -1396.25,-171.25 -1321.25,-246.25
AVCC3.3V on Top Layer "AVCC3.3V_L01_P247" (solid, pour order 247): -1846.25,278.75 -1771.25,203.75 -1802.5,172.5 -1877.5,247.5
DVDD1.2V on Top Layer "DVDD1.2V_L01_P255" (solid, pour order 255): -1428.75,203.75 -1353.75,278.75 -1322.5,247.5 -1397.5,172.5
DVDD1.2V on Top Layer "DVDD1.2V_L01_P251" (solid, pour order 251): -1878.75,653.75 -1803.75,728.75 -1772.5,697.5 -1847.5,622.5
AVCC3.3V on Top Layer "AVCC3.3V_L01_P259" (solid, pour order 259): -1352.5,622.5 -1427.5,697.5 -1396.25,728.75 -1321.25,653.75
AVCC3.3V on Top Layer "AVCC3.3V_L01_P258" (solid, pour order 258): -1352.5,1522.5 -1427.5,1597.5 -1396.25,1628.75 -1321.25,1553.75
DVDD1.2V on Top Layer "DVDD1.2V_L01_P250" (solid, pour order 250): -1878.75,1553.75 -1803.75,1628.75 -1772.5,1597.5 -1847.5,1522.5
DVDD1.2V on Top Layer "DVDD1.2V_L01_P254" (solid, pour order 254): -1428.75,1103.75 -1353.75,1178.75 -1322.5,1147.5 -1397.5,1072.5
AVCC3.3V on Top Layer "AVCC3.3V_L01_P246" (solid, pour order 246): -1846.25,1178.75 -1771.25,1103.75 -1802.5,1072.5 -1877.5,1147.5
AVCC on Int6 (SB) "AVCC_L07_P383" (solid, pour order 383): 94.49,-334.65 133.86,-295.28 177.17,-295.28 216.54,-334.65 275.59,-334.65 295.28,-314.96 389.76,-314.96 783.46,-708.66 2056.25,-708.66 2056.25,-511.81 1141.73,-511.81 787.4,-157.48 78.74,-157.48 0,-236.22 0,-334.65
SW+2V on Int6 (SB) "SW+2V_L07_P415" (solid, pour order 415): 2298.75,-305 2298.75,-821.25 2358.75,-821.25 2358.75,-305
VREF-PH on Int6 (SB) "VREF-PH_L07_P379" (solid, pour order 379): 0,-1781.25 0,-1400.94 360.94,-1040 767.72,-1040 767.72,-1781.25
XADCVCC on Int6 (SB) "XADCVCC_L07_P381" (solid, pour order 381): 55.12,-15.75 55.12,-102.36 488.19,-102.36 610.24,19.68 610.24,295.28 590.55,314.96 551.18,314.96 531.5,295.28 531.5,51.18 464.57,-15.75
AVTT on Int6 (SB) "AVTT_L07_P382" (solid, pour order 382): 98.43,-354.33 137.8,-314.96 177.17,-314.96 216.54,-354.33 275.59,-354.33 295.28,-334.65 383.86,-334.65 777.56,-728.35 2056.25,-728.35 2056.25,-905.51 1023.62,-905.51 452.76,-905.51 0,-452.76 0,-354.33
SENS_120f_N on Int6 (SB) "SENS_120F_N_L07_P367" (solid, pour order 367): 1978.35,1162.5 1978.35,1594.49 1456.69,1594.49 1456.69,1162.5
VREG on Int5 (ST) "VREG_L06_P378" (solid, pour order 378): 1993.75,1037.5 1993.75,1850 1437.5,1850 1437.5,1037.5
GND on Int1 (GND) (split plane): 113 vertices, not listed, extent -3579.9,-2467.4 3387.78,1861.25
VREF-COM on Int2 (AVDD) (split plane): 94 vertices, not listed, extent -3579.9,-2290.24 -1939.81,1861.25
COM1&2 on Int2 (AVDD) (split plane): 22 vertices, not listed, extent -3027.41,-227.41 -2110.09,1861.25
COM3&4 on Int2 (AVDD) (split plane): 24 vertices, not listed, extent -3033.66,-1789.91 -2110.09,-10.09
VCCAUX on Int2 (AVDD) (split plane): 55 vertices, not listed, extent -2092.1,-1964.91 2714.91,1861.25
EXTGND on Int2 (AVDD) (split plane): 124 vertices, not listed, extent -1843.53,-2467.4 3387.78,1861.25
NetC124_1 on Int2 (AVDD) (split plane): 19 vertices, not listed, extent 2460.09,-502.41 3252.41,1227.41
NetC123_1 on Int2 (AVDD) (split plane): 3252.41,-1770.82 3233.32,-1789.91 2460.09,-1789.91 2460.09,-522.59 3252.41,-522.59
AGND on Int3 (DVDD) (split plane): 52 vertices, not listed, extent -3579.9,-2290.24 -1939.81,1861.25
EXTGND on Int3 (DVDD) (split plane): 140 vertices, not listed, extent -1843.53,-2467.4 3387.78,1861.25
AGND on Int3 (DVDD) (split plane): -2110.09,-1783.32 -2116.68,-1789.91 -2845.82,-1789.91 -2852.41,-1783.32 -2852.41,1861.25 -2110.09,1861.25
DVDD1.2V on Int3 (DVDD) (split plane): 68 vertices, not listed, extent -2092.1,-1964.91 2439.91,1861.25
VCC2 on Int3 (DVDD) (split plane): 58 vertices, not listed, extent -1164.91,-1539.91 2714.91,1861.25
12VA on Int3 (DVDD) (split plane): 23 vertices, not listed, extent 2460.09,-1789.91 3252.41,1227.41
AVCC1V8 on Int3 (DVDD) (split plane): 39 vertices, not listed, extent 527.59,457.59 1577.41,1427.41
VCC1V0 on Int3 (DVDD) (split plane): 80 vertices, not listed, extent 10.09,-186.76 2264.91,1577.41
AGND on Int4 (GND) (split plane): 44 vertices, not listed, extent -3579.9,-2290.24 -1939.81,1861.25
GND on Int4 (GND) (split plane): 184 vertices, not listed, extent -2089.91,-1964.91 3252.41,1861.25
EXTGND on Int4 (GND) (split plane): 97 vertices, not listed, extent -1843.53,-2467.4 3387.78,764.91
XADCGND on Int4 (GND) (split plane): 101 vertices, not listed, extent 110.09,-1539.91 2364.91,1861.25
12V on Int4 (GND) (split plane): 45 vertices, not listed, extent 2385.09,785.09 3387.78,1861.25
EXTGND on Int8 (AGND) (split plane): 97 vertices, not listed, extent -1843.53,-2467.4 3387.78,764.91
AGND on Int8 (AGND) (split plane): 96 vertices, not listed, extent -3579.9,-2290.24 2439.91,1861.25
GND on Int8 (AGND) (split plane): 67 vertices, not listed, extent -1164.91,-1789.91 3252.41,1861.25
12V on Int8 (AGND) (split plane): 30 vertices, not listed, extent 2385.09,785.09 3387.78,1861.25
+7V on Int7 (AVCC) (split plane): 120 vertices, not listed, extent -3579.9,-2290.24 2439.91,1861.25
AVCC3.3V on Int7 (AVCC) (split plane): 43 vertices, not listed, extent -2089.91,-1789.91 2383.66,1861.25
EXTGND on Int7 (AVCC) (split plane): 125 vertices, not listed, extent -1843.53,-2467.4 3387.78,1861.25
VCC2V5 on Int7 (AVCC) (split plane): 32 vertices, not listed, extent -1164.91,-1352.41 2714.91,1861.25
GND on Int7 (AVCC) (split plane): 22 vertices, not listed, extent 2460.09,-1789.91 3252.41,1227.41
-7V on Int9 (VCCA) (split plane): 117 vertices, not listed, extent -3579.9,-2290.24 2439.91,1861.25
VCCA3.3V on Int9 (VCCA) (split plane): 43 vertices, not listed, extent -2089.92,-1789.91 2383.66,1861.25
EXTGND on Int9 (VCCA) (split plane): 133 vertices, not listed, extent -1843.53,-2467.4 3387.78,1861.25
VCC on Int9 (VCCA) (split plane): 31 vertices, not listed, extent -1164.91,-1352.41 2714.91,1861.25
GND on Int9 (VCCA) (split plane): 27 vertices, not listed, extent 2460.09,-1789.91 3252.41,1227.41
GND on Int10 (GND) (split plane): 113 vertices, not listed, extent -3579.9,-2467.4 3387.78,1861.25

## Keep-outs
Top Layer:
  rectangle: -3600,1042.5 -3100,1867.5
  rectangle: -477.5,-1985.53 3407.87,-1946.16
  region: -3600,-2312.32 -3009.45,-2312.32 ccw(c-3009.45,-2310.33) -3007.47,-2310.33 -3007.47,-1987.51 -2288.99,-1987.51 -2288.99,-2174.51 ccw(c-2287.01,-2174.51) -2287.01,-2176.49 -1972.05,-2176.49 ccw(c-1972.05,-2174.51) -1970.06,-2174.51 -1970.06,-2057.38 cw(c-1900.2,-2057.38) -1830.33,-2057.38 ccw(c-1828.35,-2057.38) -1826.36,-2057.38 -1826.36,-1946.16 ccw(c-1828.35,-1946.16) -1828.35,-1944.18 -3600,-1944.18 ccw(c-3600,-1946.16) -3601.98,-1946.16 -3601.98,-2310.33 ccw(c-3600,-2310.33)
Bottom Layer:
  rectangle: -477.5,-1985.53 3407.5,-1946.16
  rectangle: -3600,1042.5 -3100,1867.5
  region: -3600,-2312.32 -3009.45,-2312.32 ccw(c-3009.45,-2310.33) -3007.47,-2310.33 -3007.47,-1987.51 -2288.99,-1987.51 -2288.99,-2174.51 ccw(c-2287.01,-2174.51) -2287.01,-2176.49 -1972.05,-2176.49 ccw(c-1972.05,-2174.51) -1970.06,-2174.51 -1970.06,-2057.38 cw(c-1900.2,-2057.38) -1830.33,-2057.38 ccw(c-1828.35,-2057.38) -1826.36,-2057.38 -1826.36,-1946.16 ccw(c-1828.35,-1946.16) -1828.35,-1944.18 -3600,-1944.18 ccw(c-3600,-1946.16) -3601.98,-1946.16 -3601.98,-2310.33 ccw(c-3600,-2310.33)
Top Solder:
  rectangle: -2287.01,-2310.33 -1972.05,-2174.51
Bottom Solder:
  rectangle: -2287.01,-2310.33 -1972.05,-2174.51
KeepOutLayer:
  rectangle: -1787.5,-1537.5 -1412.5,-1162.5
  rectangle: -1787.5,1162.5 -1412.5,1537.5
  rectangle: -1787.5,262.5 -1412.5,637.5
  rectangle: -1787.5,-637.5 -1412.5,-262.5
  rectangle: -2287.01,-2310.33 -1972.05,-2174.51

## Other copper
Top Layer:
  rectangle net AGND: 2506.25,-537.5 2531.25,-487.5
  rectangle net GND: 2556.25,-537.5 2581.25,-487.5
  region net AGND: -3257.28,887.5 -3600,887.5 -3600,651.28 -3367.65,651.28 -3352.3,653.3 -3337.35,657.31 -3323.04,663.23 -3309.63,670.97 -3297.35,680.4 -3286.4,691.35 -3276.98,703.63 -3269.24,717.04 -3263.31,731.34 -3259.3,746.3 -3257.28,761.65 -3257.28,769.39
  region net AGND: -3257.28,-1762.5 -3600,-1762.5 -3600,-1526.28 -3375.39,-1526.28 -3367.65,-1526.28 -3352.3,-1528.3 -3337.35,-1532.31 -3323.04,-1538.23 -3309.63,-1545.97 -3297.35,-1555.4 -3286.4,-1566.35 -3276.98,-1578.63 -3269.24,-1592.04 -3263.31,-1606.34 -3259.3,-1621.3 -3257.28,-1636.65 -3257.28,-1644.39
Int8 (AGND) (plane layer: these items are gaps in the copper):
  lines w20: -1925,-1975 -800,-1975 -625,-1800 800,-1800 800,-1575 1112.5,-1575 1112.5,-1800 3237.5,-1800 3262.5,-1775 3262.5,-1700 ; 1125,1880 -1175,1880 -1175,800 -1175,-1362.5 -537.5,-1362.5 -537.5,-925 -462.5,-850 630.31,-850 1203.75,-276.56 1203.75,603.75 1287.5,687.5 2450,687.5 2450,-1800 ; 2375,1882.5 2375,1237.5 2725,1237.5 2725,800 ; 3417.5,775 3262.5,775 ; 2725,800 2725,800 ; 2725,800 2970,800 2970,1237.5 3175,1237.5 3175,862.5 3262.5,775 ; 3262.5,-1700 3262.5,775 ; 3262.5,-1700 3262.5,-1700
Int3 (DVDD) (plane layer: these items are gaps in the copper):
  lines w20: -2862.5,1882.5 -2862.5,-1787.5 -2850,-1800 -2112.5,-1800 -2100,-1787.5 -2100,1882.5 ; -1175,1880 -1175,-1362.5 1017.5,-1362.5 1205,-1550 1462.5,-1550 1462.5,-1062.5 1150,-750 1150,-330 1243.75,-236.25 1243.75,643.75 1287.5,687.5 2450,687.5 ; 236.22,161.22 236.22,-157.48 196.85,-196.85 40.35,-196.85 0,-156.5 0,275 49.7,332.57 518.95,837.5 912.5,837.5 ; 236.22,161.42 374.8,300 712.5,300 1149.61,737.11 1149.61,933.07 1266.54,1050 1550,1050 1757.5,842.5 2205,842.5 2275,912.5 2275,1472.5 2160,1587.5 1425,1587.5 1425,1437.5 ; 2345,-1800 2325,-1800 2450,-1800 2450,-800 2450,-650 ; 2375,1882.5 2375,1612.5 2637.5,1612.5 2712.6,1537.4 2712.6,1512.6 2637.5,1437.5 2637.5,1237.5 2725,1237.5 2725,800 ; -2106.25,-1793.75 -1925,-1975 -1812.5,-1975 -800,-1975 -625,-1800 800,-1800 800,-1633.12 800,-1575 1112.5,-1575 1112.5,-1708.12 1112.5,-1800 3237.5,-1800 3262.5,-1775 3262.5,775 3175,862.5 3175,1237.5 2970,1237.5 2970,800 2725,800 ; -2106.25,-1793.75 -2106.25,-1793.75 ; 912.5,837.5 912.5,1412.5 1072.5,1412.5 1200,1412.5 1200,1275 1256.25,1275 1425,1275 1425,1437.5 ; 912.5,837.5 565,490 517.5,490 517.5,447.5 660,447.5 1025,812.5 1025,1162.5 1587.5,1162.5 1587.5,1437.5 1425,1437.5 ; 2450,-650 2450,-650 ; 2450,-650 2450,687.5 ; 2450,687.5 2562.5,800 2725,800
Int2 (AVDD) (plane layer: these items are gaps in the copper):
  lines w20: -2862.5,1881.25 -2862.5,125 -3018.75,125 -3037.5,106.25 -3037.5,-237.5 -2912.5,-237.5 -2912.5,0 -2862.5,0 ; -2106.25,-1793.75 -1925,-1975 -800.78,-1975 -625.78,-1800 800,-1800 800,-1706.25 800,-1575 1112.5,-1575 1112.5,-1800 3237.5,-1800 3262.5,-1775 3262.5,775 3175,862.5 3175,1237.5 2970,1237.5 2970,800 2725,800 ; -2100,0 -2862.5,0 ; -2100,1882.5 -2100,-1787.5 -2112.5,-1800 -2850,-1800 -2862.5,-1787.5 -2862.5,-850 -3043.75,-850 -3043.75,-787.5 -3043.75,-725 -2862.5,-725 -2862.5,0 ; -1175,1880 1125,1880 ; -62.5,-1800 -50,-1800 ; 700,-1800 725,-1800 ; 2375,1882.5 2375,1237.5 2725,1237.5 2725,800 ; 2450,-512.5 3262.5,-512.5 ; 2450,-1800 2450,687.5 2562.5,800 2725,800 ; 2450,-1800 2450,-1800
Int4 (GND) (plane layer: these items are gaps in the copper):
  lines w20: -2100,1882.5 -2100,-1800 -1925,-1975 ; 2375,-1800 2450,-1800 ; 3262.5,712.5 3262.5,775 ; 3417.5,775 3262.5,775 ; -1925,-1975 -1925,-1975 ; -1925,-1975 -1831.63,-1975 -800,-1975 -625,-1800 800,-1800 800,-1665 800,-1575 1112.5,-1575 1112.5,-1740 1112.5,-1800 3237.5,-1800 3262.5,-1775 3262.5,775 ; 2375,1612.5 2375,1875 2187.5,1875 1900,1587.5 1793.13,1587.5 1212.5,1587.5 1112.5,1487.5 1112.5,805 995,687.5 762.5,687.5 687.5,612.5 687.5,437.5 565,315 452.5,315 422.5,285 422.5,85 350,12.5 137.5,12.5 100,-25 100,-100 100,-125 137.5,-162.5 350,-162.5 412.5,-225 918.75,-225 981.25,-287.5 981.25,-1326.25 1205,-1550 1462.5,-1550 1462.5,-1062.5 1150,-750 1150,-330 1243.75,-236.25 1243.75,-12.5 1837.5,-12.5 1837.5,82.5 1243.75,82.5 1243.75,643.75 1287.5,687.5 2050,687.5 2275,912.5 2275,1200 2375,1300 2375,1612.5 ; 2375,1612.5 2600,1612.5 2637.5,1612.5 2712.6,1537.4 2712.6,1512.6 2637.5,1437.5 2637.5,1237.5 2725,1237.5 2725,800 ; 2725,800 2725,800 ; 2725,800 2970,800 2970,925.08 2970,1237.5 3175,1237.5 3175,862.5 3262.5,775
Int7 (AVCC) (plane layer: these items are gaps in the copper):
  lines w20: -2100,1882.5 -2100,-1687.5 -2100,-1702.5 -2100,-1800 -912.5,-1800 -725,-1612.5 187.5,-1612.5 887.5,-912.5 1845,-912.5 1845,-1743.75 2393.75,-1743.75 2393.75,87.5 1243.75,87.5 1243.75,643.75 1287.5,687.5 1288.78,687.5 1990.63,687.5 2449.04,687.5 2450,688.46 ; -1900,-1975 -800,-1975 -625,-1800 800,-1800 800,-1690 800,-1575 1112.5,-1575 1112.5,-1730 1112.5,-1800 2450,-1800 ; -1175,1880 -1175,-1362.5 -847.97,-1362.5 -537.5,-1362.5 117.81,-1362.5 1243.75,-236.56 1243.75,642.5 ; 2325,-1800 2450,-1800 ; 2375,-1800 3237.5,-1800 3262.5,-1775 3262.5,775 3175,862.5 3175,1237.5 2970,1237.5 2970,800 2725,800 ; 2375,1882.5 2375,1237.5 2725,1237.5 2725,800 ; 2450,630 2450,-1746.25 2450,-1800 ; 2450,-1800 2450,-542.5 2450,-512.5 2450,687.5 2562.5,800 2725,800
Int9 (VCCA) (plane layer: these items are gaps in the copper):
  lines w20: -2100,1882.5 -2100,-1800 -912.5,-1800 -725,-1612.5 187.5,-1612.5 887.5,-912.5 1845,-912.5 1845,-1461.25 1845,-1743.75 2310,-1743.75 2393.75,-1743.75 2393.75,87.5 1243.75,87.5 ; -1900,-1975 -800,-1975 -625,-1800 ; -1175,1880 -1175,-1362.5 -831.25,-1362.5 -537.5,-1362.5 117.81,-1362.5 1188.73,-291.58 1243.75,-236.56 1243.75,87.5 ; 765,-1800 -625,-1800 ; 2374.02,-1800 3237.5,-1800 3262.5,-1775 3262.5,775 3175,862.5 3175,1237.5 2970,1237.5 2970,800 2725,800 ; 2375,1882.5 2375,1237.5 2725,1237.5 2725,800 ; 2450,-512.5 2450,-510 ; 2474.02,-1800 2475,-1799.02 ; -625,-1800 800,-1800 800,-1575 ; 800,-1575 1041.87,-1575 1112.5,-1575 ; 800,-1575 1112.5,-1575 ; 1112.5,-1800 1112.5,-1575 ; 1112.5,-1800 1112.5,-1575 ; 1112.5,-1800 1845,-1800 2450,-1800 ; 1112.5,-1800 2450,-1800 ; 1243.75,87.5 1243.75,643.75 1287.5,687.5 1990.63,687.5 2450,687.5 ; 2450,-1800 2450,687.5 ; 2450,-1800 2450,-1743.75 2450,687.5 ; 2450,687.5 2562.5,800 2725,800 ; 2725,800 2725,800
Int1 (GND) (plane layer: these items are gaps in the copper):
  lines w20: 2970,800 2970,800 ; 3262.5,775 3262.5,775
Int10 (GND) (plane layer: these items are gaps in the copper):
  lines w20: 2970,800 2970,800

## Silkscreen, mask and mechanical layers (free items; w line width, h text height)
Top Overlay:
  lines w10: -2100,1882.5 -2100,-1800 -2062.5,-1800 -1312.5,-1800 -1200,-1687.5 -1175,-1662.5 -1175,1880 ; -1900,-1975 -800,-1975 -625.02,-1800.02 800,-1800.02 800,-1611.42 800.39,-1611.02 ; 962.5,1882.5 962.5,712.5 2212.5,712.5 ; 1111.42,-1593.31 1111.42,-1750 1111.42,-1800.02 2212.5,-1800.02 ; 2212.5,-1052.5 2212.5,-700 ; 2212.5,-1037.5 2212.5,-1800.02 ; 2375,1882.5 2375,1865 2375,800 ; 2450,-1800 2450,675.25 ; 2450,-700 2212.5,-700 ; 3275,-512.5 2450,-512.5 2212.5,-512.5 2212.5,-597.5 ; 2212.5,-1800 3250,-1800 3275,-1775 3275,762.5 3237.5,800 2375,800 ; 2212.5,-700 2212.5,-597.5 ; 2212.5,-597.5 2212.5,762.5 2250,800 2375,800
  text "FAN" at 1042.17,1837.2 h40
  text "AUX" at -1140.43,1828.66 h40
  text "CLK" at -1137.63,1780.95 h40
  text "INPUT" at -1155.35,1737.41 h40
  text "12V" at 995.28,1674.65 h40
  text "GND" at 1087.15,1674.7 h40
  text "D2200368" at -3575,1662.5 h70
  text "LIGO DAC32" at -3575,1600 h70
  text "rev 2" at -3575,1537.5 h70
  text "JTAG" at -457.51,1465.15 h40
Mechanical 1:
  lines w3.94: -3600,-2310.33 -3600,1888.48 3407.87,1888.48 3407.87,-1985.53 -1029.13,-1985.53 -1029.13,-2467.82 -1048.82,-2487.5 -1292.91,-2487.5 -1312.6,-2467.82 -1312.6,-2194.19 ccw(c-1350,-2194.19) -1387.4,-2194.19 -1387.4,-2467.82 -1407.09,-2487.5 -1808.66,-2487.5 -1828.35,-2467.82 -1828.35,-2057.38 ccw(c-1900.2,-2057.38) -1972.05,-2057.38 -1972.05,-2310.33 -2287.01,-2310.33 -2287.01,-1985.53 -3009.45,-1985.53 -3009.45,-2310.33 -3600,-2310.33
Mechanical7:
  lines w3.94: -3600,-1946.16 -3600,-2310.33 -3009.45,-2310.33 -3009.45,-1985.53 -2287.01,-1985.53 -2287.01,-2174.51 -1972.05,-2174.51 -1972.05,-2057.38 cw(c-1900.2,-2057.38) -1828.35,-2057.38 -1828.35,-1946.16 ; -3590.16,-1995.37 -1818.5,-1995.37
PCI-SIG Dimensions:
  lines w3.94: -3645,-1413.25 -3810.75,-1413.25 -3810.77,-1444.78 -3826.52,-1444.78 -3858.01,-1413.29 -3858.01,638.29 -3826.52,669.78 -3810.77,669.78 -3810.77,638.25 -3641.52,638.25 -3641.48,638.29 -3641.48,870.57 ; -3641.46,-1645.57 -3176.91,-1645.57 -3176.91,870.57 ; -3641.46,-1642.5 -3641.46,-1413.25 ; -3641.47,870.56 -3176.9,870.56
Mechanical15:
  lines w1.97: -3869.8,-1649.51 -3172.95,-1649.51 -3172.95,874.51 -3869.8,874.51 -3869.8,-1649.51
  lines w3.94: -3359.69,-387.5 -3320.32,-387.5 ; -3340,-407.19 -3340,-367.82

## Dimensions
-3600,-2487.5 to -3600,1888.48 on PCI-SIG Dimensions
-3600,-2310.33 to -3600,1888.48 on PCI-SIG Dimensions
-3600,1888.48 to 3407.87,1902.26 on PCI-SIG Dimensions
